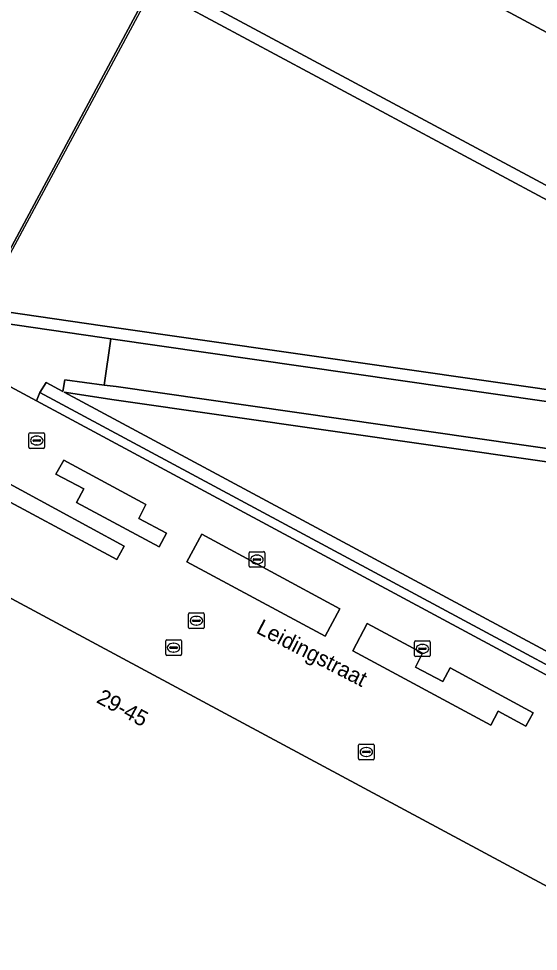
# Model space of a CAD drawing. Extents: x 159489 to 160304, y 383825 to 384531.
# Drawn here: x 159735.7 to 159768.9, y 384277.9 to 384337.5 of the extents above; entities that cross this region are included whole.
import ezdxf

# ---------------------------------------------------------------- set-up
doc = ezdxf.new("R2010")
doc.units = 0
for name, color, linetype in [('IMGEO_Groenvoorziening', 7, 'Continuous'), ('IMGEO_Kolk', 7, 'Continuous'), ('IMGEO_Openbare_ruimte_label', 7, 'Continuous'), ('IMGEO_Pand', 7, 'Continuous'), ('IMGEO_Pand_nummerreeks', 7, 'Continuous'), ('IMGEO_Pand_overbouw', 7, 'Continuous'), ('IMGEO_Rioolput', 7, 'Continuous'), ('IMGEO_Terreindeel_open', 7, 'Continuous'), ('IMGEO_Voetpad_gesloten', 7, 'Continuous'), ('IMGEO_Voetpad_halfverhard', 7, 'Continuous'), ('IMGEO_Voetpad_open', 7, 'Continuous')]:
    doc.layers.add(name, color=color, linetype=linetype)

msp = doc.modelspace()

# ---------------------------------------------------------------- linework, layer by layer
at = {"layer": 'IMGEO_Groenvoorziening'}
for points in [[(159744.661, 384303.794), (159745.133, 384304.667), (159743.36, 384305.599), (159743.815, 384306.496), (159738.566, 384309.328), (159738.071, 384308.431), (159739.861, 384307.508), (159739.387, 384306.629)], [(159733.627, 384308.609), (159733.153, 384307.722), (159741.96, 384302.978), (159742.427, 384303.848)], [(159755.25, 384298.097), (159756.186, 384299.844), (159747.382, 384304.61), (159746.437, 384302.844)], [(159765.83, 384292.409), (159766.307, 384293.288), (159768.068, 384292.342), (159768.545, 384293.198), (159763.245, 384296.062), (159762.766, 384295.182), (159761.017, 384296.115), (159761.471, 384296.996), (159757.951, 384298.901), (159757.017, 384297.162)]]:
    msp.add_lwpolyline(points, close=True, dxfattribs=at)
at = {"layer": 'IMGEO_Kolk'}
for p, q in [((159736.345, 384310.164), (159736.345, 384311.016)), ((159736.42, 384311.09), (159737.272, 384311.09)), ((159737.346, 384311.016), (159737.346, 384310.164)), ((159736.604, 384310.584), (159736.604, 384310.596)), ((159737.042, 384310.547), (159736.644, 384310.547)), ((159736.647, 384310.633), (159737.045, 384310.633)), ((159736.833, 384310.87), (159736.858, 384310.87)), ((159737.088, 384310.596), (159737.088, 384310.584)), ((159737.272, 384310.09), (159736.42, 384310.09)), ((159736.856, 384310.31), (159736.831, 384310.31)), ((159750.402, 384302.562), (159750.402, 384303.414)), ((159750.477, 384303.488), (159751.329, 384303.488)), ((159750.89, 384303.268), (159750.915, 384303.268)), ((159751.403, 384303.414), (159751.403, 384302.562)), ((159750.661, 384302.982), (159750.661, 384302.994)), ((159751.099, 384302.945), (159750.701, 384302.945)), ((159750.704, 384303.031), (159751.102, 384303.031)), ((159750.913, 384302.708), (159750.888, 384302.708)), ((159751.145, 384302.994), (159751.145, 384302.982)), ((159751.329, 384302.488), (159750.477, 384302.488)), ((159745.079, 384296.928), (159745.079, 384297.78)), ((159745.154, 384297.854), (159746.006, 384297.854)), ((159745.338, 384297.348), (159745.338, 384297.36)), ((159745.776, 384297.311), (159745.378, 384297.311)), ((159745.381, 384297.397), (159745.779, 384297.397)), ((159745.567, 384297.634), (159745.592, 384297.634)), ((159745.822, 384297.36), (159745.822, 384297.348)), ((159746.08, 384297.78), (159746.08, 384296.928)), ((159760.968, 384296.855), (159760.968, 384297.707)), ((159761.043, 384297.781), (159761.895, 384297.781)), ((159761.27, 384297.324), (159761.668, 384297.324)), ((159761.456, 384297.561), (159761.481, 384297.561)), ((159761.969, 384297.707), (159761.969, 384296.855)), ((159746.006, 384296.854), (159745.154, 384296.854)), ((159745.59, 384297.074), (159745.565, 384297.074)), ((159761.895, 384296.781), (159761.043, 384296.781)), ((159761.227, 384297.275), (159761.227, 384297.287)), ((159761.665, 384297.238), (159761.267, 384297.238)), ((159761.479, 384297.001), (159761.454, 384297.001)), ((159761.711, 384297.287), (159761.711, 384297.275)), ((159757.39, 384290.263), (159757.39, 384291.115)), ((159757.465, 384291.189), (159758.317, 384291.189)), ((159757.878, 384290.969), (159757.903, 384290.969)), ((159758.391, 384291.115), (159758.391, 384290.263)), ((159758.317, 384290.189), (159757.465, 384290.189)), ((159757.649, 384290.683), (159757.649, 384290.695)), ((159758.087, 384290.646), (159757.689, 384290.646)), ((159757.692, 384290.732), (159758.09, 384290.732)), ((159757.901, 384290.409), (159757.876, 384290.409)), ((159758.133, 384290.695), (159758.133, 384290.683))]:
    msp.add_line(p, q, dxfattribs=at)
for points in [[(159736.345, 384310.164), (159736.345, 384311.016)], [(159736.42, 384311.09), (159737.272, 384311.09)], [(159737.346, 384311.016), (159737.346, 384310.164)], [(159737.272, 384310.09), (159736.42, 384310.09)], [(159750.402, 384302.562), (159750.402, 384303.414)], [(159750.477, 384303.488), (159751.329, 384303.488)], [(159751.403, 384303.414), (159751.403, 384302.562)], [(159751.329, 384302.488), (159750.477, 384302.488)], [(159745.079, 384296.928), (159745.079, 384297.78)], [(159745.154, 384297.854), (159746.006, 384297.854)], [(159746.08, 384297.78), (159746.08, 384296.928)], [(159760.968, 384296.855), (159760.968, 384297.707)], [(159761.043, 384297.781), (159761.895, 384297.781)], [(159761.969, 384297.707), (159761.969, 384296.855)], [(159746.006, 384296.854), (159745.154, 384296.854)], [(159761.895, 384296.781), (159761.043, 384296.781)], [(159757.39, 384290.263), (159757.39, 384291.115)], [(159757.465, 384291.189), (159758.317, 384291.189)], [(159758.391, 384291.115), (159758.391, 384290.263)], [(159758.317, 384290.189), (159757.465, 384290.189)]]:
    msp.add_lwpolyline(points, dxfattribs=at)
for centre, radius, start, end in [((159736.422, 384311.014), 0.0765, 91.55205, 178.44795), ((159736.422, 384311.014), 0.0765, 91.55205, 178.44795), ((159737.27, 384311.014), 0.0765, 1.55205, 88.44795), ((159737.27, 384311.014), 0.0765, 1.55205, 88.44795), ((159736.644, 384310.593), 0.0403, 85.87752, 175.75265), ((159736.641, 384310.583), 0.0366, 178.93798, 274.71019), ((159737.045, 384310.59), 0.043, 264.86636, 352.45326), ((159737.049, 384310.595), 0.0386, 1.73085, 96.63898), ((159736.422, 384310.166), 0.0765, 181.55205, 268.44795), ((159736.422, 384310.166), 0.0765, 181.55205, 268.44795), ((159737.27, 384310.166), 0.0765, 271.55205, 358.44795), ((159737.27, 384310.166), 0.0765, 271.55205, 358.44795), ((159750.479, 384303.412), 0.0765, 91.55205, 178.44795), ((159750.479, 384303.412), 0.0765, 91.55205, 178.44795), ((159751.327, 384303.412), 0.0765, 1.55205, 88.44795), ((159751.327, 384303.412), 0.0765, 1.55205, 88.44795), ((159750.701, 384302.991), 0.0403, 85.87752, 175.75265), ((159750.698, 384302.981), 0.0366, 178.93798, 274.71019), ((159751.102, 384302.988), 0.043, 264.86636, 352.45326), ((159751.106, 384302.993), 0.0386, 1.73085, 96.63898), ((159750.479, 384302.564), 0.0765, 181.55205, 268.44795), ((159750.479, 384302.564), 0.0765, 181.55205, 268.44795), ((159751.327, 384302.564), 0.0765, 271.55205, 358.44795), ((159751.327, 384302.564), 0.0765, 271.55205, 358.44795), ((159745.156, 384297.778), 0.0765, 91.55205, 178.44795), ((159745.156, 384297.778), 0.0765, 91.55205, 178.44795), ((159745.378, 384297.357), 0.0403, 85.87752, 175.75265), ((159745.375, 384297.347), 0.0366, 178.93798, 274.71019), ((159745.779, 384297.354), 0.043, 264.86636, 352.45326), ((159745.783, 384297.359), 0.0386, 1.73085, 96.63898), ((159746.004, 384297.778), 0.0765, 1.55205, 88.44795), ((159746.004, 384297.778), 0.0765, 1.55205, 88.44795), ((159761.045, 384297.705), 0.0765, 91.55205, 178.44795), ((159761.045, 384297.705), 0.0765, 91.55205, 178.44795), ((159761.267, 384297.284), 0.0403, 85.87752, 175.75265), ((159761.672, 384297.286), 0.0386, 1.73085, 96.63898), ((159761.893, 384297.705), 0.0765, 1.55205, 88.44795), ((159761.893, 384297.705), 0.0765, 1.55205, 88.44795), ((159745.156, 384296.93), 0.0765, 181.55205, 268.44795), ((159745.156, 384296.93), 0.0765, 181.55205, 268.44795), ((159746.004, 384296.93), 0.0765, 271.55205, 358.44795), ((159746.004, 384296.93), 0.0765, 271.55205, 358.44795), ((159761.045, 384296.857), 0.0765, 181.55205, 268.44795), ((159761.045, 384296.857), 0.0765, 181.55205, 268.44795), ((159761.264, 384297.274), 0.0366, 178.93798, 274.71019), ((159761.668, 384297.281), 0.043, 264.86636, 352.45326), ((159761.893, 384296.857), 0.0765, 271.55205, 358.44795), ((159761.893, 384296.857), 0.0765, 271.55205, 358.44795), ((159757.467, 384291.113), 0.0765, 91.55205, 178.44795), ((159757.467, 384291.113), 0.0765, 91.55205, 178.44795), ((159758.315, 384291.113), 0.0765, 1.55205, 88.44795), ((159758.315, 384291.113), 0.0765, 1.55205, 88.44795), ((159757.467, 384290.265), 0.0765, 181.55205, 268.44795), ((159757.467, 384290.265), 0.0765, 181.55205, 268.44795), ((159757.689, 384290.692), 0.0403, 85.87752, 175.75265), ((159757.686, 384290.682), 0.0366, 178.93798, 274.71019), ((159758.09, 384290.689), 0.043, 264.86636, 352.45326), ((159758.094, 384290.694), 0.0386, 1.73085, 96.63898), ((159758.315, 384290.265), 0.0765, 271.55205, 358.44795), ((159758.315, 384290.265), 0.0765, 271.55205, 358.44795)]:
    msp.add_arc(centre, radius, start, end, dxfattribs=at)
for centre, major_axis, ratio, start_param, end_param in [((159736.832, 384310.59), (-0.387, 0.002), 0.722429, 4.712389, 7.853982), ((159736.857, 384310.59), (-0.39, 0.002), 0.717154, 1.570796, 4.712389), ((159750.889, 384302.988), (-0.387, 0.002), 0.722429, 4.712389, 7.853982), ((159750.914, 384302.988), (-0.39, 0.002), 0.717154, 1.570796, 4.712389), ((159745.566, 384297.354), (-0.387, 0.002), 0.722429, 4.712389, 7.853982), ((159745.591, 384297.354), (-0.39, 0.002), 0.717154, 1.570796, 4.712389), ((159761.455, 384297.281), (-0.387, 0.002), 0.722429, 4.712389, 7.853982), ((159761.48, 384297.281), (-0.39, 0.002), 0.717154, 1.570796, 4.712389), ((159757.877, 384290.689), (-0.387, 0.002), 0.722429, 4.712389, 7.853982), ((159757.902, 384290.689), (-0.39, 0.002), 0.717154, 1.570796, 4.712389)]:
    msp.add_ellipse(centre, major_axis=major_axis, ratio=ratio, start_param=start_param, end_param=end_param, dxfattribs=at)
at = {"layer": 'IMGEO_Pand'}
msp.add_lwpolyline([(159783.397, 384375.103), (159766.339, 384384.271), (159766.74, 384385.035), (159762.446, 384387.363), (159762.034, 384386.593), (159757.242, 384389.159), (159757.112, 384388.916), (159743.621, 384396.119), (159743.741, 384396.343), (159735.557, 384400.786), (159735.425, 384400.573), (159735.575, 384400.48), (159735.43, 384400.212), (159716.859, 384365.689), (159716.722, 384365.762), (159716.246, 384364.892), (159716.4, 384364.81), (159721.137, 384362.285), (159721.26, 384362.516), (159807.547, 384316.187)], dxfattribs=at)
for points in [[(159744.495, 384340.27), (159745.463, 384342.08), (159719.159, 384356.157), (159718.221, 384354.406), (159717.843, 384353.7), (159708.49, 384336.235), (159734.794, 384322.143), (159744.117, 384339.565)], [(159747.439, 384293.915), (159731.551, 384302.457), (159731.779, 384302.882), (159730.898, 384303.355), (159730.67, 384302.93), (159730.406, 384303.072), (159715.868, 384275.99), (159766.025, 384249.054), (159765.572, 384248.208), (159765.546, 384248.161), (159779.824, 384240.489), (159781.812, 384244.448), (159783.972, 384248.491), (159794.191, 384267.623), (159794.673, 384268.525)]]:
    msp.add_lwpolyline(points, close=True, dxfattribs=at)
at = {"layer": 'IMGEO_Pand_overbouw'}
for points in [[(159772.845, 384392.873), (159746.364, 384407.132), (159719.057, 384356.211), (159708.316, 384336.181), (159708.428, 384336.121), (159728.589, 384325.319), (159734.596, 384322.101), (159734.859, 384321.96), (159745.598, 384342.008)], [(159745.463, 384342.08), (159744.495, 384340.27), (159744.117, 384339.565), (159734.794, 384322.143), (159708.49, 384336.235), (159717.843, 384353.7), (159718.221, 384354.406), (159719.159, 384356.157)]]:
    msp.add_lwpolyline(points, close=True, dxfattribs=at)
at = {"layer": 'IMGEO_Rioolput'}
for p, q in [((159746.54, 384298.648), (159746.54, 384299.5)), ((159746.615, 384299.574), (159747.467, 384299.574)), ((159746.842, 384299.117), (159747.24, 384299.117)), ((159747.028, 384299.354), (159747.053, 384299.354)), ((159747.541, 384299.5), (159747.541, 384298.648)), ((159747.467, 384298.574), (159746.615, 384298.574)), ((159746.799, 384299.068), (159746.799, 384299.08)), ((159747.237, 384299.031), (159746.839, 384299.031)), ((159747.051, 384298.794), (159747.026, 384298.794)), ((159747.283, 384299.08), (159747.283, 384299.068))]:
    msp.add_line(p, q, dxfattribs=at)
for points in [[(159746.54, 384298.648), (159746.54, 384299.5)], [(159746.615, 384299.574), (159747.467, 384299.574)], [(159747.541, 384299.5), (159747.541, 384298.648)], [(159747.467, 384298.574), (159746.615, 384298.574)]]:
    msp.add_lwpolyline(points, dxfattribs=at)
for centre, radius, start, end in [((159746.617, 384299.498), 0.0765, 91.55205, 178.44795), ((159746.617, 384299.498), 0.0765, 91.55205, 178.44795), ((159746.839, 384299.077), 0.0403, 85.87752, 175.75265), ((159747.244, 384299.079), 0.0386, 1.73085, 96.63898), ((159747.465, 384299.498), 0.0765, 1.55205, 88.44795), ((159747.465, 384299.498), 0.0765, 1.55205, 88.44795), ((159746.617, 384298.65), 0.0765, 181.55205, 268.44795), ((159746.617, 384298.65), 0.0765, 181.55205, 268.44795), ((159746.836, 384299.067), 0.0366, 178.93798, 274.71019), ((159747.24, 384299.074), 0.043, 264.86636, 352.45326), ((159747.465, 384298.65), 0.0765, 271.55205, 358.44795), ((159747.465, 384298.65), 0.0765, 271.55205, 358.44795)]:
    msp.add_arc(centre, radius, start, end, dxfattribs=at)
for centre, major_axis, ratio, start_param, end_param in [((159747.027, 384299.074), (-0.387, 0.002), 0.722429, 4.712389, 7.853982), ((159747.052, 384299.074), (-0.39, 0.002), 0.717154, 1.570796, 4.712389)]:
    msp.add_ellipse(centre, major_axis=major_axis, ratio=ratio, start_param=start_param, end_param=end_param, dxfattribs=at)
at = {"layer": 'IMGEO_Terreindeel_open'}
for points in [[(159797.007, 384309.896), (159741.046, 384317.91), (159726.866, 384319.977), (159700.707, 384334.064), (159712.762, 384356.443), (159717.843, 384353.7), (159718.221, 384354.406), (159712.442, 384357.532), (159699.61, 384333.72), (159726.44, 384319.286), (159726.801, 384319.234), (159741.002, 384317.183), (159741.576, 384317.086), (159796.909, 384309.117), (159800.043, 384308.652), (159800.185, 384309.411), (159801.736, 384308.601), (159802.101, 384309.308), (159781.459, 384320.418), (159744.495, 384340.27), (159744.117, 384339.565), (159781.262, 384319.609), (159800.092, 384309.462)], [(159741.908, 384314.033), (159741.156, 384314.134), (159738.631, 384314.476), (159738.511, 384313.717), (159737.45, 384314.29), (159737.034, 384313.652), (159800.661, 384279.441), (159813.426, 384303.207), (159812.032, 384303.968), (159802.893, 384305.271), (159796.705, 384306.154), (159796.491, 384306.184)], [(159737.034, 384313.652), (159736.839, 384313.125), (159800.352, 384278.938), (159800.661, 384279.441)], [(159796.588, 384305.334), (159805.581, 384304.082), (159811.651, 384303.266), (159812.348, 384302.895), (159800.337, 384280.498), (159738.603, 384313.672), (159741.793, 384313.181)]]:
    msp.add_lwpolyline(points, close=True, dxfattribs=at)
at = {"layer": 'IMGEO_Voetpad_gesloten'}
for points in [[(159744.117, 384339.565), (159734.794, 384322.143), (159708.49, 384336.235), (159717.843, 384353.7), (159712.762, 384356.443), (159700.707, 384334.064), (159726.866, 384319.977), (159741.046, 384317.91), (159797.007, 384309.896), (159800.092, 384309.462), (159781.262, 384319.609)], [(159741.793, 384313.181), (159738.603, 384313.672), (159800.337, 384280.498), (159812.348, 384302.895), (159811.651, 384303.266), (159805.581, 384304.082), (159796.588, 384305.334)]]:
    msp.add_lwpolyline(points, close=True, dxfattribs=at)
at = {"layer": 'IMGEO_Voetpad_halfverhard'}
msp.add_lwpolyline([(159807.288, 384315.703), (159807.547, 384316.187), (159721.26, 384362.516), (159721.137, 384362.285), (159716.4, 384364.81), (159712.638, 384357.799), (159712.442, 384357.532), (159718.221, 384354.406), (159719.159, 384356.157), (159745.463, 384342.08), (159744.495, 384340.27), (159781.459, 384320.418), (159802.101, 384309.308), (159803.465, 384308.568)], close=True, dxfattribs=at)
at = {"layer": 'IMGEO_Voetpad_open'}
for points in [[(159800.352, 384278.938), (159736.839, 384313.125), (159726.485, 384318.691), (159699.381, 384333.281)], [(159693.74, 384322.781), (159717.376, 384310.076), (159717.604, 384310.502), (159718.485, 384310.029), (159718.256, 384309.603), (159718.52, 384309.461), (159724.134, 384306.443), (159723.803, 384305.826), (159724.517, 384305.443), (159724.846, 384306.056), (159730.406, 384303.072), (159730.67, 384302.93), (159730.898, 384303.355), (159731.779, 384302.882), (159731.551, 384302.457), (159747.439, 384293.915), (159794.673, 384268.525)]]:
    msp.add_lwpolyline(points, dxfattribs=at)
for points in [[(159726.801, 384319.234), (159726.485, 384318.691), (159736.839, 384313.125), (159737.034, 384313.652), (159737.45, 384314.29), (159738.511, 384313.717), (159738.631, 384314.476), (159741.156, 384314.134), (159741.576, 384317.086), (159741.002, 384317.183)], [(159741.576, 384317.086), (159741.156, 384314.134), (159741.908, 384314.033), (159796.491, 384306.184), (159796.909, 384309.117)], [(159744.661, 384303.794), (159739.387, 384306.629), (159739.861, 384307.508), (159738.071, 384308.431), (159738.566, 384309.328), (159743.815, 384306.496), (159743.36, 384305.599), (159745.133, 384304.667)], [(159733.627, 384308.609), (159742.427, 384303.848), (159741.96, 384302.978), (159733.153, 384307.722)], [(159755.25, 384298.097), (159746.437, 384302.844), (159747.382, 384304.61), (159756.186, 384299.844)], [(159765.83, 384292.409), (159757.017, 384297.162), (159757.951, 384298.901), (159761.471, 384296.996), (159761.017, 384296.115), (159762.766, 384295.182), (159763.245, 384296.062), (159768.545, 384293.198), (159768.068, 384292.342), (159766.307, 384293.288)]]:
    msp.add_lwpolyline(points, close=True, dxfattribs=at)

# ---------------------------------------------------------------- texts
at = {"layer": 'IMGEO_Openbare_ruimte_label'}
msp.add_text('Leidingstraat', height=1, rotation=332.79408, dxfattribs=at).set_placement((159750.789, 384298.327))
at = {"layer": 'IMGEO_Pand_nummerreeks'}
msp.add_text('29-45', height=1, rotation=331.73599, dxfattribs=at).set_placement((159740.594, 384293.883))

doc.saveas('drawing.dxf')
